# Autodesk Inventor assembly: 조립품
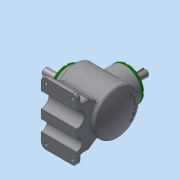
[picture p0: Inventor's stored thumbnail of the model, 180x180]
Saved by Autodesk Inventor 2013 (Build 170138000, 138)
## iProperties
Created: 2018-08
Part Number: 조립품
Document SubType Name: Assembly
Designer: dgall
Author: dgall
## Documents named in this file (14)
- C:\Users\dgall\Desktop\480807V1008\조립품.iam
- C:\Users\dgall\Desktop\480807V1008\본체.ipt
- C:\Users\dgall\Desktop\480807V1008\메인 베벨기어.ipt
- C:\Users\dgall\Desktop\480807V1008\메인 축.ipt
- 메인 축.ipt
- C:\Users\dgall\Desktop\480807V1008\베어링 6203.ipt
- C:\Users\dgall\Desktop\480807V1008\볼트 M4.ipt
- C:\Users\dgall\Desktop\480807V1008\서브 베벨기어.ipt
- C:\Users\dgall\Desktop\480807V1008\서브 축.ipt
- 서브 축.ipt
- C:\Users\dgall\Desktop\480807V1008\오일실 17 32 8.ipt
- C:\Users\dgall\Desktop\480807V1008\커버.ipt
- C:\Users\dgall\Desktop\480807V1008\키 4x4.ipt
- C:\Users\dgall\Desktop\480807V1008\키 5x5.ipt
